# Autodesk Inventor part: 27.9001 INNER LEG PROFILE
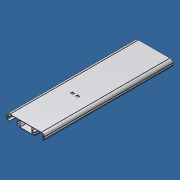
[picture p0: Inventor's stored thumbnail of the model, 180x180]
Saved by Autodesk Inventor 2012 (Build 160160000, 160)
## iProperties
Created: 2013-10
Part Number: 27.9001 INNER LEG PROFILE
Material: Aluminum-6061
Document SubType Name: Modeling
Designer: Admin
Density: 2.71 g/cm^3
Mass: 1776.94 g
Surface Area: 5156.22 cm^2
Volume: 655.697 cm^3
Author: Admin
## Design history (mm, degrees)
node "H58-0010 INNER ATU LEG_658-020001"
sketch "Sketch1"
  geometry: A1 r 5.9 centre (-9.3, -15.8) between (-5.416, -11.359) and (-11.92, -10.514) reference; A2 r 5.9 centre (154.7, -15.8) between (150.816, -20.241) and (157.32, -21.086) reference; 3 further points
  constraints: 2 coincident
hole "m8 taps" sketch "Sketch1" at (-9.3, -15.8), (154.7, -15.8) diameter "d0" = 7.647; stored, may be unused: countersink angle "d4" = 90 deg, drill point angle "d6" = 118 deg; dims "d1" = 30, "d2" = 4, "d3" = 2, "d5" = 35
node "Base1"
body "Solid1"
